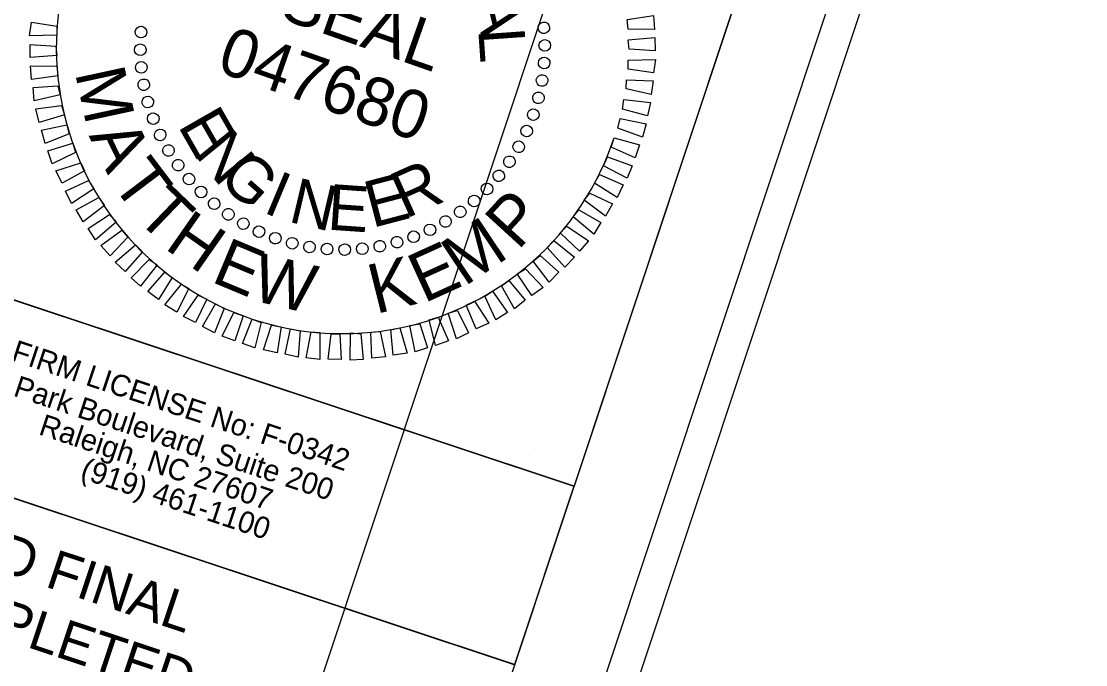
# Model space of a CAD drawing. Extents: x 2296288 to 2297455, y 600637 to 601606.
# Drawn here: x 2297365.9 to 2297455, y 601175.7 to 601229.6 of the extents above; entities that cross this region are included whole.
import ezdxf

# ---------------------------------------------------------------- set-up
doc = ezdxf.new("R2010")
doc.units = 0
for name, color, linetype in [('Exist DTM Crownline Cogo Point CELL', 7, 'Continuous'), ('Exist DTM Drainline Cogo Comment', 7, 'Continuous'), ('Exist DTM Drainline Cogo Point CELL', 7, 'Continuous'), ('Exist Roads Curbs Cogo Comment', 7, 'Continuous'), ('Exist Roads Curbs Cogo Number', 7, 'Continuous'), ('Exist Roads Curbs Cogo Point CELL', 7, 'Continuous'), ('Exist Roads EOP Cogo Comment', 7, 'Continuous'), ('Exist Roads EOP Other Cogo Elevation', 7, 'Continuous'), ('Exist Roads EOP Other Cogo Point CELL', 7, 'Continuous')]:
    doc.layers.add(name, color=color, linetype=linetype)

msp = doc.modelspace()

# ---------------------------------------------------------------- linework, layer by layer
at = {"layer": 'Exist DTM Crownline Cogo Point CELL'}
msp.add_arc((2297392.802, 601227.377), 23.962, 161.60824, 341.60824, dxfattribs=at)
at = {"layer": 'Exist DTM Drainline Cogo Comment'}
for points in [[(2297440.604, 601276.062), (2296586.575, 601560.023), (2296387.802, 600962.203), (2297241.831, 600678.242)], [(2297376.56, 601273.614), (2297433.496, 601254.683), (2297412.199, 601190.63), (2297355.263, 601209.561)]]:
    msp.add_lwpolyline(points, close=True, dxfattribs=at)
at = {"layer": 'Exist DTM Drainline Cogo Point CELL'}
msp.add_lwpolyline([(2297421.637, 601266.561), (2296596.076, 601541.057), (2296406.768, 600971.704), (2297232.33, 600697.208)], close=True, dxfattribs=at)
at = {"layer": 'Exist Roads Curbs Cogo Comment'}
msp.add_line((2297293.33, 601213.557), (2297407.223, 601175.688), dxfattribs=at)
at = {"layer": 'Exist Roads Curbs Cogo Number'}
msp.add_lwpolyline([(2297455.016, 601287.078), (2296496.225, 601605.872), (2296287.987, 600979.583), (2297246.777, 600660.79)], close=True, dxfattribs=at)
at = {"layer": 'Exist Roads Curbs Cogo Point CELL'}
msp.add_lwpolyline([(2297448.204, 601275.148), (2296499.377, 601590.629), (2296299.639, 600989.904), (2297248.465, 600674.423)], close=True, dxfattribs=at)
at = {"layer": 'Exist Roads EOP Other Cogo Elevation'}
for p, q in [((2297375.906, 601228.656), (2297375.906, 601228.656)), ((2297409.674, 601229.023), (2297409.674, 601229.023)), ((2297392.802, 601227.377), (2297392.802, 601227.377)), ((2297409.761, 601227.572), (2297409.761, 601227.572)), ((2297375.843, 601227.183), (2297375.843, 601227.183)), ((2297375.93, 601225.732), (2297375.93, 601225.732)), ((2297409.698, 601226.099), (2297409.698, 601226.099)), ((2297409.485, 601224.604), (2297409.485, 601224.604)), ((2297376.155, 601224.27), (2297376.155, 601224.27)), ((2297409.22, 601223.163), (2297409.22, 601223.163)), ((2297376.487, 601222.808), (2297376.487, 601222.808)), ((2297376.915, 601221.421), (2297376.915, 601221.421)), ((2297408.783, 601221.744), (2297408.783, 601221.744)), ((2297408.218, 601220.366), (2297408.218, 601220.366)), ((2297377.524, 601220.044), (2297377.524, 601220.044)), ((2297378.197, 601218.753), (2297378.197, 601218.753)), ((2297407.536, 601219.064), (2297407.536, 601219.064)), ((2297379.031, 601217.516), (2297379.031, 601217.516)), ((2297406.801, 601217.814), (2297406.801, 601217.814)), ((2297405.905, 601216.618), (2297405.905, 601216.618)), ((2297379.918, 601216.332), (2297379.918, 601216.332)), ((2297380.954, 601215.276), (2297380.954, 601215.276)), ((2297404.903, 601215.529), (2297404.903, 601215.529)), ((2297382.043, 601214.274), (2297382.043, 601214.274)), ((2297403.847, 601214.493), (2297403.847, 601214.493)), ((2297383.239, 601213.378), (2297383.239, 601213.378)), ((2297402.663, 601213.606), (2297402.663, 601213.606)), ((2297384.488, 601212.643), (2297384.488, 601212.643)), ((2297401.426, 601212.773), (2297401.426, 601212.773)), ((2297385.791, 601211.961), (2297385.791, 601211.961)), ((2297387.168, 601211.396), (2297387.168, 601211.396)), ((2297398.758, 601211.49), (2297398.758, 601211.49)), ((2297400.135, 601212.1), (2297400.135, 601212.1)), ((2297388.588, 601210.96), (2297388.588, 601210.96)), ((2297390.029, 601210.694), (2297390.029, 601210.694)), ((2297391.523, 601210.482), (2297391.523, 601210.482)), ((2297392.996, 601210.419), (2297392.996, 601210.419)), ((2297394.447, 601210.505), (2297394.447, 601210.505)), ((2297395.909, 601210.73), (2297395.909, 601210.73)), ((2297397.371, 601211.062), (2297397.371, 601211.062)), ((2297408.751, 601193.834), (2297408.751, 601193.834))]:
    msp.add_line(p, q, dxfattribs=at)
for points in [[(2297416.632, 601229.733), (2297418.841, 601230.065), (2297418.917, 601228.902), (2297416.718, 601228.922)], [(2297368.894, 601228.427), (2297366.6, 601228.371), (2297366.759, 601229.492), (2297368.894, 601229.174)], [(2297416.708, 601228.036), (2297418.939, 601228.219), (2297418.961, 601227.109), (2297416.805, 601227.257)], [(2297368.895, 601226.719), (2297366.665, 601226.536), (2297366.643, 601227.646), (2297368.799, 601227.498)], [(2297416.709, 601226.328), (2297419.004, 601226.383), (2297418.845, 601225.262), (2297416.71, 601225.581)], [(2297368.971, 601225.022), (2297366.762, 601224.69), (2297366.687, 601225.853), (2297368.885, 601225.833)], [(2297416.583, 601224.663), (2297418.803, 601224.601), (2297418.633, 601223.448), (2297416.551, 601223.927)], [(2297369.154, 601223.432), (2297366.988, 601222.907), (2297366.902, 601224.039), (2297368.972, 601224.168)], [(2297416.36, 601223.03), (2297418.591, 601222.786), (2297418.325, 601221.665), (2297416.232, 601222.219)], [(2297369.518, 601221.746), (2297367.416, 601221.093), (2297367.127, 601222.256), (2297369.283, 601222.536)], [(2297416.041, 601221.429), (2297418.208, 601220.993), (2297417.91, 601219.883), (2297415.849, 601220.639)], [(2297369.914, 601220.156), (2297367.898, 601219.333), (2297367.598, 601220.464), (2297369.732, 601220.892)], [(2297370.46, 601218.588), (2297368.507, 601217.636), (2297368.122, 601218.725), (2297370.224, 601219.377)], [(2297415.54, 601219.817), (2297417.654, 601219.221), (2297417.292, 601218.132), (2297415.285, 601219.048)], [(2297371.197, 601217.062), (2297369.32, 601216.015), (2297368.807, 601217.039), (2297370.887, 601217.734)], [(2297414.976, 601218.226), (2297417.036, 601217.47), (2297416.621, 601216.434), (2297414.656, 601217.479)], [(2297414.305, 601216.742), (2297416.29, 601215.869), (2297415.8, 601214.822), (2297413.889, 601216.027)], [(2297371.978, 601215.558), (2297370.111, 601214.329), (2297369.598, 601215.353), (2297371.529, 601216.24)], [(2297372.865, 601214.16), (2297371.094, 601212.793), (2297370.495, 601213.774), (2297372.405, 601214.811)], [(2297413.505, 601215.194), (2297415.406, 601214.278), (2297414.82, 601213.263), (2297413.026, 601214.607)], [(2297373.858, 601212.763), (2297372.12, 601211.278), (2297371.511, 601212.227), (2297373.281, 601213.381)], [(2297412.578, 601213.795), (2297414.425, 601212.719), (2297413.849, 601211.736), (2297412.098, 601213.208)], [(2297411.586, 601212.418), (2297413.38, 601211.181), (2297412.634, 601210.327), (2297411.01, 601211.862)], [(2297374.82, 601211.483), (2297373.348, 601209.945), (2297372.568, 601210.809), (2297374.339, 601212.069)], [(2297376.048, 601210.256), (2297374.619, 601208.633), (2297373.775, 601209.412), (2297375.46, 601210.843)], [(2297410.477, 601211.222), (2297412.218, 601209.825), (2297411.408, 601208.992), (2297409.923, 601210.623)], [(2297377.287, 601209.169), (2297375.879, 601207.396), (2297375.11, 601208.078), (2297376.625, 601209.638)], [(2297409.347, 601209.961), (2297410.906, 601208.554), (2297410.096, 601207.721), (2297408.76, 601209.481)], [(2297378.536, 601208.113), (2297377.396, 601206.287), (2297376.509, 601206.938), (2297377.938, 601208.561)], [(2297408.12, 601208.84), (2297409.594, 601207.283), (2297408.656, 601206.599), (2297407.416, 601208.434)], [(2297406.734, 601207.878), (2297408.101, 601206.214), (2297407.184, 601205.488), (2297406.115, 601207.408)], [(2297379.935, 601207.186), (2297378.923, 601205.21), (2297377.919, 601205.829), (2297379.316, 601207.569)], [(2297405.368, 601206.981), (2297406.618, 601205.178), (2297405.637, 601204.579), (2297404.728, 601206.553)], [(2297381.451, 601206.29), (2297380.482, 601204.336), (2297379.478, 601204.848), (2297380.715, 601206.642)], [(2297382.903, 601205.523), (2297382.083, 601203.484), (2297381.09, 601204.027), (2297382.177, 601205.907)], [(2297403.843, 601206.136), (2297405.039, 601204.28), (2297403.994, 601203.81), (2297403.16, 601205.794)], [(2297384.473, 601204.894), (2297383.781, 601202.813), (2297382.734, 601203.196), (2297383.715, 601205.182)], [(2297402.413, 601205.367), (2297403.354, 601203.489), (2297402.33, 601202.976), (2297401.656, 601205.121)], [(2297385.999, 601204.351), (2297385.467, 601202.216), (2297384.421, 601202.6), (2297385.241, 601204.639)], [(2297387.654, 601203.979), (2297387.325, 601201.812), (2297386.193, 601202.046), (2297386.853, 601204.138)], [(2297399.266, 601204.244), (2297399.907, 601202.216), (2297398.872, 601201.885), (2297398.433, 601204.094)], [(2297400.802, 601204.8), (2297401.668, 601202.805), (2297400.58, 601202.42), (2297400.055, 601204.586)], [(2297389.255, 601203.66), (2297389.086, 601201.44), (2297387.997, 601201.695), (2297388.454, 601203.819)], [(2297390.909, 601203.501), (2297390.911, 601201.26), (2297389.748, 601201.398), (2297390.184, 601203.565)], [(2297392.585, 601203.406), (2297392.683, 601201.24), (2297391.594, 601201.282), (2297391.838, 601203.406)], [(2297394.325, 601203.397), (2297394.54, 601201.263), (2297393.451, 601201.198), (2297393.46, 601203.471)], [(2297395.958, 601203.601), (2297396.386, 601201.467), (2297395.244, 601201.348), (2297395.157, 601203.547)], [(2297397.59, 601203.912), (2297398.2, 601201.788), (2297397.037, 601201.606), (2297396.854, 601203.73)]]:
    msp.add_lwpolyline(points, close=True, dxfattribs=at)
for centre, major_axis in [((2297375.923, 601228.674), (-0.485, 0.037)), ((2297409.65, 601229.032), (0.484, 0.047)), ((2297375.874, 601227.198), (-0.486, -0.005)), ((2297409.73, 601227.557), (0.486, 0.005)), ((2297409.681, 601226.081), (0.485, -0.037)), ((2297375.954, 601225.723), (-0.484, -0.047)), ((2297376.162, 601224.261), (-0.478, -0.089)), ((2297409.504, 601224.615), (0.479, -0.079)), ((2297409.2, 601223.17), (0.471, -0.121)), ((2297376.497, 601222.822), (-0.468, -0.131)), ((2297376.956, 601221.419), (-0.455, -0.171)), ((2297408.77, 601221.756), (0.458, -0.161)), ((2297377.536, 601220.06), (-0.438, -0.21)), ((2297408.22, 601220.386), (0.443, -0.201)), ((2297378.232, 601218.758), (-0.418, -0.247)), ((2297407.552, 601219.069), (0.423, -0.239)), ((2297406.772, 601217.815), (0.401, -0.275)), ((2297379.038, 601217.521), (-0.395, -0.283)), ((2297379.95, 601216.359), (-0.369, -0.316)), ((2297405.885, 601216.634), (0.376, -0.308)), ((2297380.959, 601215.28), (-0.34, -0.347)), ((2297404.899, 601215.534), (0.347, -0.34)), ((2297382.058, 601214.294), (-0.308, -0.376)), ((2297403.821, 601214.525), (0.316, -0.369)), ((2297383.24, 601213.408), (-0.275, -0.401)), ((2297402.659, 601213.614), (0.283, -0.395)), ((2297384.493, 601212.627), (-0.239, -0.423)), ((2297401.421, 601212.807), (0.247, -0.418)), ((2297385.811, 601211.959), (-0.201, -0.443)), ((2297400.119, 601212.111), (0.21, -0.438)), ((2297387.181, 601211.409), (-0.161, -0.458)), ((2297388.594, 601210.98), (-0.121, -0.471)), ((2297395.918, 601210.738), (0.089, -0.478)), ((2297397.357, 601211.073), (0.131, -0.468)), ((2297398.76, 601211.532), (0.171, -0.455)), ((2297390.039, 601210.675), (-0.079, -0.479)), ((2297391.505, 601210.498), (-0.037, -0.485)), ((2297392.982, 601210.449), (0.005, -0.486)), ((2297394.456, 601210.529), (0.047, -0.484))]:
    msp.add_ellipse(centre, major_axis=major_axis, ratio=0.999708, dxfattribs=at)
at = {"layer": 'Exist Roads EOP Other Cogo Point CELL'}
msp.add_lwpolyline([(2297298.299, 601228.501), (2297412.17, 601190.64), (2297407.201, 601175.695), (2297293.33, 601213.557)], close=True, dxfattribs=at)

# ---------------------------------------------------------------- texts
at = {"layer": 'Exist Roads Curbs Cogo Comment'}
for s, p in [('DOCUMENT NOT CONSIDERED FINAL', (2297303.368, 601203.678)), ('UNLESS ALL SIGNATURES COMPLETED', (2297298.815, 601199.627))]:
    msp.add_text(s, height=3.30002, rotation=341.60824, dxfattribs=at).set_placement(p)
at = {"layer": 'Exist Roads EOP Cogo Comment'}
for s, p in [('NC FIRM LICENSE No: F-0342', (2297361.046, 601202.514)), ('5438 Wade Park Boulevard, Suite 200', (2297352.835, 601202.328)), ('Raleigh, NC 27607', (2297367.278, 601195.006)), ('(919) 461-1100', (2297370.761, 601191.329))]:
    msp.add_text(s, height=1.80001, rotation=341.60824, dxfattribs=at).set_placement(p)
at = {"layer": 'Exist Roads EOP Other Cogo Elevation'}
for s, height, rotation, p in [('SEAL', 4.0489, 340.60824, (2297387.346, 601229.903)), ('A', 3.916, 283.36851, (2297403.642, 601231.527)), ('047680', 4.0501, 340.60824, (2297382.137, 601225.438)), ('L', 3.879, 274.00909, (2297404.156, 601228.901)), ('M', 4.162, 282.20279, (2297370.394, 601225.287)), ('E', 3.927, 299.88513, (2297378.964, 601220.846)), ('A', 4.183, 296.01773, (2297371.542, 601219.997)), ('N', 3.902, 309.2422, (2297380.311, 601218.478)), ('T', 4.159, 307.09476, (2297373.356, 601216.05)), ('G', 3.864, 318.59848, (2297382.266, 601216.227)), ('R', 3.929, 24.08965, (2297398.053, 601213.005)), ('I', 3.808, 337.30944, (2297386.056, 601213.615)), ('E', 3.905, 14.73233, (2297395.279, 601212.256)), ('T', 4.122, 316.09474, (2297375.367, 601213.147)), ('N', 3.809, 346.66463, (2297388.17, 601212.806)), ('E', 3.831, 356.02, (2297391.469, 601212.136)), ('P', 4.133, 47.59046, (2297407.482, 601210.32)), ('H', 4.084, 325.09473, (2297377.808, 601210.595)), ('M', 4.18, 33.77552, (2297402.984, 601207.308)), ('E', 4.051, 337.33615, (2297381.707, 601207.798)), ('E', 4.18, 24.46084, (2297399.602, 601205.924)), ('W', 4.052, 346.65084, (2297385.022, 601206.26)), ('K', 4.151, 13.95028, (2297395.574, 601205.044))]:
    msp.add_text(s, height=height, rotation=rotation, dxfattribs=at).set_placement(p)

doc.saveas('drawing.dxf')
